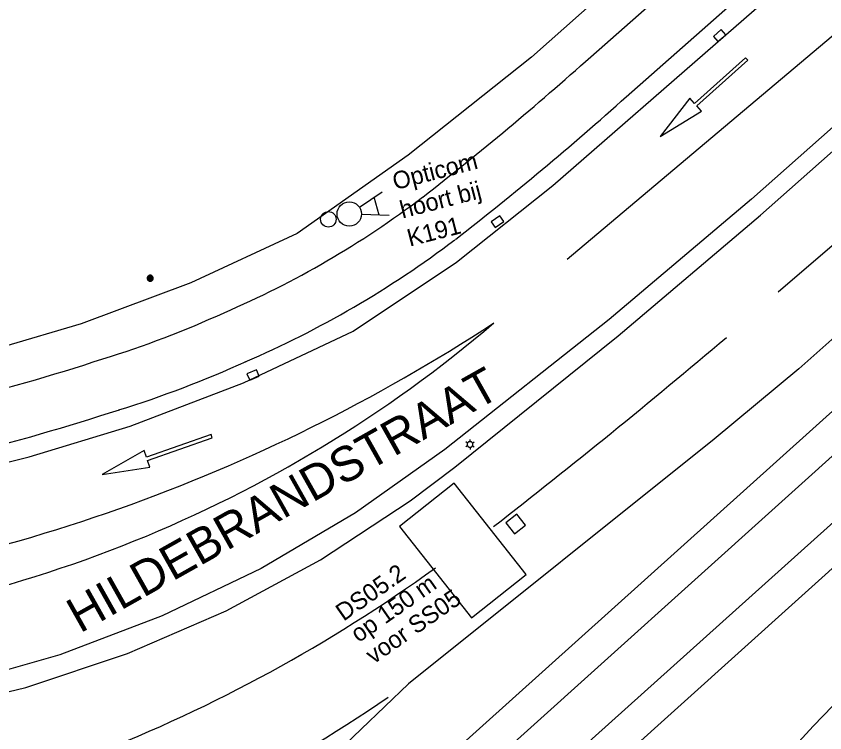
# Model space of a CAD drawing. Extents: x 81065 to 81486, y 452384 to 452681.
# Drawn here: x 81090.96 to 81125.76, y 452408.42 to 452439.25 of the extents above; entities that cross this region are included whole.
import ezdxf

# ---------------------------------------------------------------- set-up
doc = ezdxf.new("R2010")
doc.units = 0
for name, color, linetype in [('B-BH-AL-TOPOGRAFIE_STRAATNAAM-S', 7, 'Continuous'), ('B-BH-GR-BOOM-S', 7, 'Continuous'), ('B-BH-IE-MEUBILAIR_WEGMEUBILAIR_LICHTMAST-S', 7, 'Continuous'), ('B-BH-RI-GWA_RIOOLPUT-S', 7, 'Continuous'), ('B-BH-VH-KANTOPSLUITING-GV', 7, 'Continuous'), ('B-SB-OG-WEG_SPOOR_TRAM-G', 7, 'Continuous'), ('B-SRI-KOLK_COMBINATIE-S', 7, 'Continuous'), ('B-WE-VW-MARKERING_LANGS_STREEP_13_010-G', 7, 'Continuous'), ('B-WE-VW-MARKERING_LANGS_STREEP_DOORGETROKKEN_010-G', 7, 'Continuous'), ('B-WE-VW-MARKERING_PIJL-S', 7, 'Continuous'), ('N-OI-KL-VRI_LUS_DETECTIE_SELECTIEF-G', 7, 'Continuous'), ('N-OI-KL-VRI_LUS_DETECTIE_SELECTIEF-T18', 7, 'Continuous'), ('N-WE-VW-VRI_ARMATUUR-S', 7, 'Continuous'), ('N-WE-VW-VRI_ARMATUUR-T18', 7, 'Continuous'), ('N-WE-VW-VRI_MAST-S', 7, 'Continuous')]:
    doc.layers.add(name, color=color, linetype=linetype)

msp = doc.modelspace()

# ---------------------------------------------------------------- linework, layer by layer
at = {"layer": 'B-BH-GR-BOOM-S'}
for points in [[(81096.6, 452427.98), (81096.601, 452427.966), (81096.603, 452427.953), (81096.606, 452427.94), (81096.611, 452427.928), (81096.617, 452427.916), (81096.625, 452427.904), (81096.633, 452427.894), (81096.643, 452427.884), (81096.653, 452427.876), (81096.665, 452427.868), (81096.677, 452427.862), (81096.689, 452427.857), (81096.702, 452427.854), (81096.715, 452427.852), (81096.729, 452427.851), (81096.742, 452427.852), (81096.756, 452427.854), (81096.769, 452427.857), (81096.781, 452427.862), (81096.793, 452427.868), (81096.805, 452427.876), (81096.815, 452427.884), (81096.825, 452427.894), (81096.833, 452427.904), (81096.841, 452427.916), (81096.847, 452427.928), (81096.851, 452427.94), (81096.855, 452427.953), (81096.857, 452427.966), (81096.858, 452427.98), (81096.857, 452427.993), (81096.855, 452428.007), (81096.851, 452428.02), (81096.847, 452428.032), (81096.841, 452428.044), (81096.833, 452428.056), (81096.825, 452428.066), (81096.815, 452428.076), (81096.805, 452428.084), (81096.793, 452428.092), (81096.781, 452428.098), (81096.769, 452428.102), (81096.756, 452428.106), (81096.742, 452428.108), (81096.729, 452428.109), (81096.715, 452428.108), (81096.702, 452428.106), (81096.689, 452428.102), (81096.677, 452428.098), (81096.665, 452428.092), (81096.653, 452428.084), (81096.643, 452428.076), (81096.633, 452428.066), (81096.625, 452428.056), (81096.617, 452428.044), (81096.611, 452428.032), (81096.606, 452428.02), (81096.603, 452428.007), (81096.601, 452427.993), (81096.6, 452427.98)], [(81096.625, 452427.98), (81096.625, 452427.969), (81096.627, 452427.958), (81096.63, 452427.948), (81096.634, 452427.937), (81096.638, 452427.928), (81096.644, 452427.919), (81096.651, 452427.91), (81096.659, 452427.902), (81096.668, 452427.895), (81096.677, 452427.889), (81096.686, 452427.885), (81096.697, 452427.881), (81096.707, 452427.878), (81096.718, 452427.876), (81096.729, 452427.876), (81096.74, 452427.876), (81096.751, 452427.878), (81096.761, 452427.881), (81096.771, 452427.885), (81096.781, 452427.889), (81096.79, 452427.895), (81096.799, 452427.902), (81096.807, 452427.91), (81096.813, 452427.919), (81096.819, 452427.928), (81096.824, 452427.937), (81096.828, 452427.948), (81096.831, 452427.958), (81096.833, 452427.969), (81096.833, 452427.98), (81096.833, 452427.991), (81096.831, 452428.002), (81096.828, 452428.012), (81096.824, 452428.022), (81096.819, 452428.032), (81096.813, 452428.041), (81096.807, 452428.05), (81096.799, 452428.058), (81096.79, 452428.064), (81096.781, 452428.07), (81096.771, 452428.075), (81096.761, 452428.079), (81096.751, 452428.082), (81096.74, 452428.084), (81096.729, 452428.084), (81096.718, 452428.084), (81096.707, 452428.082), (81096.697, 452428.079), (81096.686, 452428.075), (81096.677, 452428.07), (81096.668, 452428.064), (81096.659, 452428.058), (81096.651, 452428.05), (81096.644, 452428.041), (81096.638, 452428.032), (81096.634, 452428.022), (81096.63, 452428.012), (81096.627, 452428.002), (81096.625, 452427.991), (81096.625, 452427.98)], [(81096.647, 452427.98), (81096.648, 452427.971), (81096.649, 452427.963), (81096.651, 452427.955), (81096.654, 452427.947), (81096.658, 452427.939), (81096.663, 452427.932), (81096.668, 452427.925), (81096.674, 452427.919), (81096.681, 452427.914), (81096.688, 452427.909), (81096.696, 452427.905), (81096.704, 452427.902), (81096.712, 452427.9), (81096.72, 452427.899), (81096.729, 452427.898), (81096.737, 452427.899), (81096.746, 452427.9), (81096.754, 452427.902), (81096.762, 452427.905), (81096.77, 452427.909), (81096.777, 452427.914), (81096.784, 452427.919), (81096.79, 452427.925), (81096.795, 452427.932), (81096.8, 452427.939), (81096.803, 452427.947), (81096.807, 452427.955), (81096.809, 452427.963), (81096.81, 452427.971), (81096.811, 452427.98), (81096.81, 452427.988), (81096.809, 452427.997), (81096.807, 452428.005), (81096.803, 452428.013), (81096.8, 452428.021), (81096.795, 452428.028), (81096.79, 452428.035), (81096.784, 452428.041), (81096.777, 452428.046), (81096.77, 452428.051), (81096.762, 452428.054), (81096.754, 452428.058), (81096.746, 452428.06), (81096.737, 452428.061), (81096.729, 452428.062), (81096.72, 452428.061), (81096.712, 452428.06), (81096.704, 452428.058), (81096.696, 452428.054), (81096.688, 452428.051), (81096.681, 452428.046), (81096.674, 452428.041), (81096.668, 452428.035), (81096.663, 452428.028), (81096.658, 452428.021), (81096.654, 452428.013), (81096.651, 452428.005), (81096.649, 452427.997), (81096.648, 452427.988), (81096.647, 452427.98)], [(81096.67, 452427.98), (81096.671, 452427.974), (81096.672, 452427.968), (81096.673, 452427.962), (81096.675, 452427.956), (81096.678, 452427.951), (81096.682, 452427.945), (81096.685, 452427.941), (81096.69, 452427.936), (81096.694, 452427.933), (81096.7, 452427.929), (81096.705, 452427.926), (81096.711, 452427.924), (81096.717, 452427.923), (81096.723, 452427.922), (81096.729, 452427.921), (81096.735, 452427.922), (81096.741, 452427.923), (81096.747, 452427.924), (81096.753, 452427.926), (81096.758, 452427.929), (81096.763, 452427.933), (81096.768, 452427.936), (81096.773, 452427.941), (81096.776, 452427.945), (81096.78, 452427.951), (81096.783, 452427.956), (81096.785, 452427.962), (81096.786, 452427.968), (81096.787, 452427.974), (81096.788, 452427.98), (81096.787, 452427.986), (81096.786, 452427.992), (81096.785, 452427.998), (81096.783, 452428.004), (81096.78, 452428.009), (81096.776, 452428.014), (81096.773, 452428.019), (81096.768, 452428.024), (81096.763, 452428.027), (81096.758, 452428.031), (81096.753, 452428.034), (81096.747, 452428.036), (81096.741, 452428.037), (81096.735, 452428.038), (81096.729, 452428.039), (81096.723, 452428.038), (81096.717, 452428.037), (81096.711, 452428.036), (81096.705, 452428.034), (81096.7, 452428.031), (81096.694, 452428.027), (81096.69, 452428.024), (81096.685, 452428.019), (81096.682, 452428.014), (81096.678, 452428.009), (81096.675, 452428.004), (81096.673, 452427.998), (81096.672, 452427.992), (81096.671, 452427.986), (81096.67, 452427.98)], [(81096.693, 452427.98), (81096.693, 452427.976), (81096.694, 452427.973), (81096.695, 452427.969), (81096.696, 452427.965), (81096.698, 452427.962), (81096.7, 452427.959), (81096.702, 452427.956), (81096.705, 452427.953), (81096.708, 452427.951), (81096.711, 452427.949), (81096.714, 452427.947), (81096.718, 452427.946), (81096.722, 452427.945), (81096.725, 452427.944), (81096.729, 452427.944), (81096.733, 452427.944), (81096.736, 452427.945), (81096.74, 452427.946), (81096.744, 452427.947), (81096.747, 452427.949), (81096.75, 452427.951), (81096.753, 452427.953), (81096.755, 452427.956), (81096.758, 452427.959), (81096.76, 452427.962), (81096.762, 452427.965), (81096.763, 452427.969), (81096.764, 452427.973), (81096.765, 452427.976), (81096.765, 452427.98), (81096.765, 452427.984), (81096.764, 452427.987), (81096.763, 452427.991), (81096.762, 452427.995), (81096.76, 452427.998), (81096.758, 452428.001), (81096.755, 452428.004), (81096.753, 452428.006), (81096.75, 452428.009), (81096.747, 452428.011), (81096.744, 452428.013), (81096.74, 452428.014), (81096.736, 452428.015), (81096.733, 452428.016), (81096.729, 452428.016), (81096.725, 452428.016), (81096.722, 452428.015), (81096.718, 452428.014), (81096.714, 452428.013), (81096.711, 452428.011), (81096.708, 452428.009), (81096.705, 452428.006), (81096.702, 452428.004), (81096.7, 452428.001), (81096.698, 452427.998), (81096.696, 452427.995), (81096.695, 452427.991), (81096.694, 452427.987), (81096.693, 452427.984), (81096.693, 452427.98)], [(81096.716, 452427.98), (81096.716, 452427.979), (81096.716, 452427.977), (81096.717, 452427.976), (81096.717, 452427.975), (81096.718, 452427.974), (81096.719, 452427.972), (81096.719, 452427.971), (81096.72, 452427.97), (81096.721, 452427.97), (81096.723, 452427.969), (81096.724, 452427.968), (81096.725, 452427.968), (81096.726, 452427.967), (81096.728, 452427.967), (81096.729, 452427.967), (81096.73, 452427.967), (81096.732, 452427.967), (81096.733, 452427.968), (81096.734, 452427.968), (81096.735, 452427.969), (81096.737, 452427.97), (81096.738, 452427.97), (81096.739, 452427.971), (81096.739, 452427.972), (81096.74, 452427.974), (81096.741, 452427.975), (81096.741, 452427.976), (81096.742, 452427.977), (81096.742, 452427.979), (81096.742, 452427.98), (81096.742, 452427.981), (81096.742, 452427.983), (81096.741, 452427.984), (81096.741, 452427.985), (81096.74, 452427.986), (81096.739, 452427.988), (81096.739, 452427.989), (81096.738, 452427.99), (81096.737, 452427.99), (81096.735, 452427.991), (81096.734, 452427.992), (81096.733, 452427.992), (81096.732, 452427.993), (81096.73, 452427.993), (81096.729, 452427.993), (81096.728, 452427.993), (81096.726, 452427.993), (81096.725, 452427.992), (81096.724, 452427.992), (81096.723, 452427.991), (81096.721, 452427.99), (81096.72, 452427.99), (81096.719, 452427.989), (81096.719, 452427.988), (81096.718, 452427.986), (81096.717, 452427.985), (81096.717, 452427.984), (81096.716, 452427.983), (81096.716, 452427.981), (81096.716, 452427.98)]]:
    msp.add_lwpolyline(points, dxfattribs=at)
at = {"layer": 'B-BH-IE-MEUBILAIR_WEGMEUBILAIR_LICHTMAST-S'}
for p, q in [((81110.386, 452420.891), (81110.307, 452420.937)), ((81110.492, 452420.952), (81110.492, 452421.044)), ((81110.597, 452420.891), (81110.677, 452420.937)), ((81110.386, 452420.769), (81110.307, 452420.723)), ((81110.492, 452420.708), (81110.492, 452420.616)), ((81110.597, 452420.769), (81110.677, 452420.723))]:
    msp.add_line(p, q, dxfattribs=at)
msp.add_lwpolyline([(81110.37, 452420.83), (81110.371, 452420.817), (81110.372, 452420.804), (81110.376, 452420.792), (81110.38, 452420.78), (81110.386, 452420.769), (81110.393, 452420.758), (81110.401, 452420.748), (81110.41, 452420.739), (81110.42, 452420.731), (81110.431, 452420.724), (81110.442, 452420.718), (81110.454, 452420.714), (81110.467, 452420.71), (81110.479, 452420.709), (81110.492, 452420.708), (81110.505, 452420.709), (81110.517, 452420.71), (81110.53, 452420.714), (81110.542, 452420.718), (81110.553, 452420.724), (81110.564, 452420.731), (81110.574, 452420.739), (81110.583, 452420.748), (81110.591, 452420.758), (81110.598, 452420.769), (81110.603, 452420.78), (81110.608, 452420.792), (81110.611, 452420.804), (81110.613, 452420.817), (81110.614, 452420.83), (81110.613, 452420.843), (81110.611, 452420.855), (81110.608, 452420.868), (81110.603, 452420.88), (81110.598, 452420.891), (81110.591, 452420.902), (81110.583, 452420.912), (81110.574, 452420.921), (81110.564, 452420.929), (81110.553, 452420.936), (81110.542, 452420.941), (81110.53, 452420.946), (81110.517, 452420.949), (81110.505, 452420.951), (81110.492, 452420.952), (81110.479, 452420.951), (81110.466, 452420.949), (81110.454, 452420.946), (81110.442, 452420.941), (81110.431, 452420.936), (81110.42, 452420.929), (81110.41, 452420.921), (81110.401, 452420.912), (81110.393, 452420.902), (81110.386, 452420.891), (81110.38, 452420.88), (81110.376, 452420.868), (81110.372, 452420.855), (81110.371, 452420.843), (81110.37, 452420.83)], dxfattribs=at)
at = {"layer": 'B-BH-RI-GWA_RIOOLPUT-S'}
for p, q in [((81112.512, 452417.832), (81112.032, 452417.459)), ((81112.884, 452417.352), (81112.512, 452417.832)), ((81112.032, 452417.459), (81112.404, 452416.98)), ((81112.404, 452416.98), (81112.884, 452417.352))]:
    msp.add_line(p, q, dxfattribs=at)
at = {"layer": 'B-BH-VH-KANTOPSLUITING-GV'}
for p, q in [((81115.685, 452437.507), (81123.533, 452444.43)), ((81117.206, 452435.782), (81125.055, 452442.705)), ((81131.086, 452429.833), (81124.643, 452424.084)), ((81124.643, 452424.084), (81120.996, 452421.057)), ((81120.996, 452421.057), (81107.845, 452410.527)), ((81100.269, 452403.315), (81107.845, 452410.527))]:
    msp.add_line(p, q, dxfattribs=at)
for points in [[(81134.787, 452456.025), (81126.096, 452448.896), (81118.199, 452441.999), (81113.143, 452437.485), (81107.829, 452433.277), (81103.049, 452429.902), (81098.478, 452427.776), (81093.752, 452426.02), (81090.351, 452425.011), (81085.962, 452423.903), (81082.242, 452423.054), (81078.454, 452422.6), (81075.869, 452422.518), (81071.545, 452422.563)], [(81088.978, 452419.664), (81091.521, 452420.301), (81095.873, 452421.616), (81100.744, 452423.479), (81105.457, 452425.71), (81109.909, 452428.671), (81114.061, 452431.966), (81121.497, 452438.457), (81129.14, 452445.115), (81137.719, 452452.145)], [(81140.808, 452446.932), (81138.398, 452445.055), (81130.765, 452438.603), (81122.603, 452431.375), (81116.484, 452426.201), (81109.408, 452420.612), (81105.563, 452417.884), (81101.501, 452415.492), (81097.25, 452413.453), (81092.842, 452411.781), (81088.309, 452410.489), (81083.682, 452409.586), (81082.95, 452409.48), (81079.983, 452409.406), (81079.607, 452409.266), (81079.514, 452408.877)], [(81079.514, 452408.877), (81079.784, 452408.581), (81079.969, 452408.559), (81082.317, 452408.609), (81086.885, 452409.295), (81091.376, 452410.373), (81095.757, 452411.836), (81099.995, 452413.672), (81104.059, 452415.868), (81107.917, 452418.407), (81109.833, 452419.856), (81116.867, 452425.502), (81122.997, 452430.688), (81131.236, 452437.985), (81139.463, 452444.873), (81141.843, 452446.719)], [(81117.537, 452400.177), (81119.063, 452401.963), (81125.277, 452408.727), (81129.835, 452413.447), (81139.202, 452422.718), (81140.996, 452424.369)]]:
    msp.add_lwpolyline(points, dxfattribs=at)
for centre, radius, start, end in [((81027.372, 452535.93), 132.236, 307.81872, 311.90087), ((81027.372, 452535.93), 134.536, 307.81872, 311.90087), ((81083.812, 452463.985), 40.798, 293.2399, 307.1569), ((81083.812, 452463.985), 43.098, 293.2399, 307.1569), ((81081.777, 452466.287), 43.727, 287.1808, 294.4993), ((81064.147, 452518.275), 98.613, 279.98509, 288.04467), ((81081.777, 452466.287), 46.027, 287.1808, 294.4993), ((81064.147, 452518.275), 100.913, 279.98509, 288.04467)]:
    msp.add_arc(centre, radius, start, end, dxfattribs=at)
at = {"layer": 'B-SB-OG-WEG_SPOOR_TRAM-G'}
for points in [[(81159.493, 452443.093), (81158.269, 452442.229), (81153.904, 452439.013), (81149.605, 452435.712), (81142.074, 452429.595), (81132.278, 452421.075), (81111.932, 452402.757)], [(81091.566, 452395.787), (81093.82, 452396.784), (81096.032, 452397.873), (81098.197, 452399.05), (81100.313, 452400.314), (81102.376, 452401.662), (81104.383, 452403.094), (81108.058, 452406.052), (81128.086, 452424.061), (81138.732, 452433.407), (81144.254, 452437.992)], [(81073.376, 452389.882), (81075.079, 452390.039), (81077.581, 452390.371), (81080.067, 452390.805), (81082.533, 452391.34), (81084.975, 452391.974), (81087.39, 452392.707), (81089.773, 452393.538), (81092.121, 452394.464), (81094.428, 452395.485), (81096.693, 452396.599), (81098.91, 452397.805), (81101.076, 452399.099), (81103.188, 452400.48), (81105.243, 452401.945), (81109.072, 452405.032), (81127.365, 452421.484), (81136.586, 452429.669)], [(81132.047, 452422.791), (81108.447, 452401.618), (81105.218, 452399.064), (81103.151, 452397.608), (81101.023, 452396.242), (81098.839, 452394.968), (81096.602, 452393.789), (81094.317, 452392.706), (81091.988, 452391.723), (81089.619, 452390.839), (81087.214, 452390.059), (81084.778, 452389.381), (81083.906, 452389.179)]]:
    msp.add_lwpolyline(points, dxfattribs=at)
at = {"layer": 'B-SRI-KOLK_COMBINATIE-S'}
for p, q in [((81121.301, 452438.675), (81120.964, 452438.381)), ((81121.495, 452438.453), (81121.301, 452438.675)), ((81120.964, 452438.381), (81121.158, 452438.158)), ((81121.158, 452438.158), (81121.495, 452438.453)), ((81111.768, 452430.662), (81111.405, 452430.401)), ((81111.941, 452430.422), (81111.768, 452430.662)), ((81111.405, 452430.401), (81111.577, 452430.161)), ((81111.577, 452430.161), (81111.941, 452430.422)), ((81101.304, 452424.045), (81100.894, 452423.865)), ((81101.423, 452423.774), (81101.304, 452424.045)), ((81100.894, 452423.865), (81101.012, 452423.595)), ((81101.012, 452423.595), (81101.423, 452423.774))]:
    msp.add_line(p, q, dxfattribs=at)
at = {"layer": 'B-WE-VW-MARKERING_LANGS_STREEP_13_010-G'}
for p, q in [((81114.675, 452428.801), (81134.259, 452445.306)), ((81123.756, 452427.393), (81136.938, 452438.777))]:
    msp.add_line(p, q, dxfattribs=at)
for centre, radius, start, end in [((80929.646, 452651.43), 296.463, 307.83867, 310.33254), ((81069.938, 452469.634), 66.74, 291.37072, 305.82624)]:
    msp.add_arc(centre, radius, start, end, dxfattribs=at)
at = {"layer": 'B-WE-VW-MARKERING_LANGS_STREEP_DOORGETROKKEN_010-G'}
for centre, radius, start, end in [((81070.288, 452488.963), 75.209, 275.73566, 303.24355), ((81074.975, 452468.865), 56.28, 273.4768, 310.4891), ((81072.901, 452459.564), 60.178, 272.15386, 304.47568)]:
    msp.add_arc(centre, radius, start, end, dxfattribs=at)
at = {"layer": 'B-WE-VW-MARKERING_PIJL-S'}
for points in [[(81118.673, 452434.082), (81120.452, 452435.167), (81120.252, 452435.391), (81122.453, 452437.356), (81122.353, 452437.468), (81120.152, 452435.503), (81119.952, 452435.727)], [(81094.655, 452419.533), (81096.713, 452419.859), (81096.614, 452420.142), (81099.397, 452421.119), (81099.348, 452421.261), (81096.564, 452420.283), (81096.465, 452420.566)]]:
    msp.add_lwpolyline(points, close=True, dxfattribs=at)
at = {"layer": 'N-OI-KL-VRI_LUS_DETECTIE_SELECTIEF-G'}
for p, q in [((81109.814, 452419.162), (81107.458, 452417.303)), ((81112.913, 452415.239), (81109.814, 452419.162)), ((81107.458, 452417.303), (81110.556, 452413.378)), ((81110.556, 452413.378), (81112.913, 452415.239))]:
    msp.add_line(p, q, dxfattribs=at)
at = {"layer": 'N-WE-VW-VRI_ARMATUUR-S'}
for p, q in [((81105.732, 452431.038), (81106.714, 452431.702)), ((81106.586, 452430.698), (81106.365, 452431.466)), ((81107.006, 452430.682), (81105.821, 452430.725))]:
    msp.add_line(p, q, dxfattribs=at)
msp.add_circle((81105.296, 452430.744), 0.526, dxfattribs=at)
at = {"layer": 'N-WE-VW-VRI_MAST-S'}
msp.add_circle((81104.396, 452430.515), 0.335, dxfattribs=at)

# ---------------------------------------------------------------- texts
at = {"layer": 'B-BH-AL-TOPOGRAFIE_STRAATNAAM-S'}
msp.add_text('HILDEBRANDSTRAAT', height=1.5, rotation=29.3683, dxfattribs=at).set_placement((81093.708, 452412.691))
at = {"layer": 'N-OI-KL-VRI_LUS_DETECTIE_SELECTIEF-T18'}
for s, p in [('DS05.2', (81105.049, 452413.205)), ('op 150 m', (81105.693, 452412.283)), ('voor SS05', (81106.337, 452411.36))]:
    msp.add_text(s, height=0.75, rotation=34.902, dxfattribs=at).set_placement(p)
at = {"layer": 'N-WE-VW-VRI_ARMATUUR-T18'}
for s, p in [('Opticom', (81107.267, 452431.77)), ('hoort bij', (81107.583, 452430.547)), ('K191', (81107.896, 452429.337))]:
    msp.add_text(s, height=0.75, rotation=14.4989, dxfattribs=at).set_placement(p)

doc.saveas('drawing.dxf')
